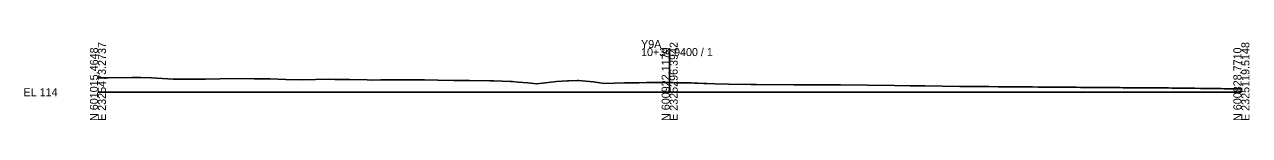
# Model space of a CAD drawing. Extents: x -26 to 2325310, y -10 to 600913.
# Drawn here: x 2774.3 to 3202.8, y -9.7 to 18.2 of the extents above; entities that cross this region are included whole.
import ezdxf

# ---------------------------------------------------------------- set-up
doc = ezdxf.new("R2010")
doc.units = 0
for name, color, linetype in [('Exist CMT Pavement', 7, 'Continuous'), ('Exist Cross Section Cell', 7, 'Continuous'), ('Exist XS Center Line Elevation Label', 7, 'Continuous'), ('Exist XS Ground Line', 7, 'Continuous'), ('Prop XS Earthwork Shape', 7, 'Continuous')]:
    doc.layers.add(name, color=color, linetype=linetype)

msp = doc.modelspace()

# ---------------------------------------------------------------- linework, layer by layer
at = {"layer": 'Exist CMT Pavement'}
for p, q in [((3000, 3.35), (3000, 3.45)), ((3000, 3.45), (3000.1, 3.45)), ((3000.1, 3.45), (3000.1, 3.35))]:
    msp.add_line(p, q, dxfattribs=at)
at = {"layer": 'Exist Cross Section Cell'}
for p, q in [((3000, 0), (3000, 15.4)), ((2800, 0), (3000, 0)), ((3000, 0), (3200, 0))]:
    msp.add_line(p, q, dxfattribs=at)
at = {"layer": 'Exist XS Ground Line'}
msp.add_lwpolyline([(2800, 4.99), (2803.75, 5.04), (2811.83, 5.12), (2815.06, 5.13), (2818.68, 5), (2826.37, 4.58), (2833.25, 4.58), (2837.68, 4.57), (2842.62, 4.68), (2848.99, 4.78), (2854.68, 4.73), (2860.3, 4.71), (2865.76, 4.49), (2871.6, 4.29), (2876.11, 4.39), (2880.56, 4.51), (2882.91, 4.49), (2887.97, 4.47), (2894.22, 4.34), (2895.67, 4.25), (2898.94, 4.35), (2899.82, 4.34), (2914.28, 4.29), (2918.86, 4.24), (2924.55, 4.05), (2930.02, 4.1), (2937.14, 3.97), (2938.52, 3.98), (2944.36, 3.77), (2945, 3.7), (2946.96, 3.52), (2950.4, 3.34), (2953.48, 2.92), (2960.39, 3.76), (2964.26, 4.03), (2964.78, 4.04), (2967.61, 4.06), (2968.15, 4.07), (2973.21, 3.58), (2977.25, 3.06), (2984.18, 3.29), (2987.8, 3.32), (2989.29, 3.33), (2991.86, 3.36), (2992.56, 3.37), (2994.94, 3.38), (2996.71, 3.38), (2997.92, 3.38), (2998.52, 3.37), (2999.44, 3.36), (3000, 3.35), (3000.33, 3.35), (3000.9, 3.35), (3002.13, 3.34), (3004.05, 3.31), (3005.75, 3.29), (3006.85, 3.26), (3007.56, 3.24), (3008.66, 3.21), (3009.37, 3.19), (3009.82, 3.17), (3011.95, 3.11), (3013.05, 3.07), (3015.94, 2.98), (3020.59, 2.88), (3028.4, 2.7), (3029.88, 2.68), (3030.4, 2.67), (3043.43, 2.59), (3052.15, 2.54), (3059.76, 2.54), (3078.65, 2.36), (3084.09, 2.22), (3089.31, 2.22), (3101.46, 2.02), (3105.02, 2), (3110.64, 1.98), (3111.6, 1.98), (3114.91, 1.95), (3117.73, 1.93), (3119.08, 1.92), (3119.75, 1.91), (3121.36, 1.9), (3122.1, 1.9), (3122.49, 1.89), (3123.75, 1.88), (3124.63, 1.87), (3125.39, 1.87), (3126.88, 1.85), (3128.87, 1.83), (3129.6, 1.82), (3131.84, 1.8), (3132.16, 1.8), (3133.07, 1.79), (3134.13, 1.79), (3134.82, 1.78), (3135.94, 1.78), (3138.01, 1.75), (3140.77, 1.74), (3141.37, 1.74), (3142.29, 1.73), (3143.75, 1.71), (3144.98, 1.7), (3146.9, 1.7), (3148.6, 1.67), (3149.7, 1.67), (3150.41, 1.66), (3151.5, 1.66), (3152.22, 1.65), (3152.68, 1.65), (3154.02, 1.63), (3155.65, 1.62), (3156.11, 1.62), (3157.64, 1.61), (3158.63, 1.6), (3160.72, 1.58), (3161.26, 1.57), (3161.6, 1.57), (3163.07, 1.57), (3164.58, 1.56), (3165.33, 1.55), (3167.56, 1.53), (3169.94, 1.52), (3170.37, 1.52), (3170.76, 1.51), (3172.7, 1.49), (3173.51, 1.49), (3173.91, 1.49), (3174.54, 1.49), (3175.65, 1.48), (3177.18, 1.47), (3177.85, 1.46), (3179, 1.45), (3180.04, 1.44), (3180.46, 1.44), (3182.77, 1.41), (3183.76, 1.39), (3185.65, 1.36), (3186.91, 1.36), (3188.39, 1.34), (3190.19, 1.3), (3191.36, 1.28), (3191.99, 1.27), (3192.98, 1.26), (3193.81, 1.25), (3194.34, 1.24), (3195.61, 1.22), (3197.58, 1.2), (3200, 1.17)], dxfattribs=at)
at = {"layer": 'Prop XS Earthwork Shape'}
msp.add_lwpolyline([(3000, 3.35), (3000.1, 3.35), (3000.1, 3.45), (3000, 3.45)], close=True, dxfattribs=at)

# ---------------------------------------------------------------- texts
at = {"layer": 'Exist Cross Section Cell'}
for s, p in [('E 2325473.2737', (2802.8, -10)), ('E 2325296.3942', (3002.8, -10)), ('E 2325119.5148', (3202.8, -10)), ('N 601015.4648', (2800, -10)), ('N 600922.1179', (3000, -10)), ('N 600828.7710', (3200, -10))]:
    msp.add_text(s, height=2.8, rotation=90, dxfattribs=at).set_placement(p)
for s, p in [('Y9A', (2990, 15.4)), ('10+34.9400 / 1', (2990, 12.6)), ('EL 114', (2774, -1.4))]:
    msp.add_text(s, height=2.8, dxfattribs=at).set_placement(p)
at = {"layer": 'Exist XS Center Line Elevation Label'}
msp.add_text('117.35', height=0.2, dxfattribs=at).set_placement((2999.65, 1.35))

doc.saveas('drawing.dxf')
